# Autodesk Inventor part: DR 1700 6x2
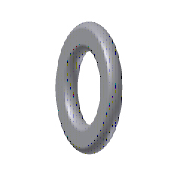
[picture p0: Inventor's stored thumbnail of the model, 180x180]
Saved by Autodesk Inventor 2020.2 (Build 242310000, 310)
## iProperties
Manager: www.cadconsulting.pl
Company: Fabian Stasiak CAD Consulting
Created: 2014-02
Part Number: DR 1700 6x2
Material: ABS-DFA-R
Description: O Ring
Document SubType Name: Modeling
Designer: F.Stasiak
Standard Revision: 1
Manufacturer: DME
Language: pl-PL
Size Designation: 6x2
Categories: <MemberInstance><Categories><Category DisplayName="Forma wtryskowa" InternalName="349578f2-f4d4-4954-8c09-8e99297a61c0" Mnemonic="MOLD"><Category DisplayName="K
Density: 1.04 g/cm^3
Appearance: Domyślna
Catalog Web Link: www.expertbooks.pl
IsCustomPart: 1
Author: F.Stasiak
Subject: Zbiór ćwiczeń. Autodesk Inventor 2020. Kurs Professional
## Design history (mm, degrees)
sketch "Sketch1"
  geometry: L1 (0, -1.4)-(0, 1.4) reference; L2 (-1, 0)-(6, 0) reference; L3 (4.6, -0.8)-(3.4, -0.8); L4 (3.4, 0.8)-(4.6, 0.8); A1 r 1 centre (4, 0) between (3.4, 0.8) and (3.4, -0.8); A2 r 1 centre (4, 0) between (4.6, 0.8) and (3.4, 0.8); A3 r 1 centre (4, 0) between (4.6, -0.8) and (4.6, 0.8); A4 r 1 centre (4, 0) between (3.4, -0.8) and (4.6, -0.8); 1 further point
  constraints: 8 point on circle, 4 centre point, 4 end point, 3 parallel, 1 point on line
  dimensions: "d3" = 8 diameter of A1.centre L1 (= dx + d2); "d9" = 2 diameter of A1 (= d2); "d20" = 1.6 distance between parallel lines of L3 L4 (= t_CS)
revolve "Revolution1" sketch "Sketch1" stored, may be unused: angle "d24" = 90 deg
sketch "Sketch2"
  geometry: L1 (-6.645, 0)-(7.668, 0) reference; L2 (0, -1.128)-(0, 1.166) reference; L3 (-4.6, 0.8)-(4.6, 0.8) reference; L4 (-4.6, -0.8)-(4.6, -0.8) reference; L5 (2.377, 0.8)-(5.623, 0.8); L6 (5.424, 0.617)-(5.3, -0.8); L7 (2.7, -0.8)-(5.3, -0.8); L8 (2.576, 0.617)-(2.7, -0.8); L9 (2.7, -0.8)-(2.7, 0.8); L10 (5.3, -0.8)-(5.3, 0.8); A1 r 1 centre (4, 0) between (4.6, -0.8) and (4.6, 0.8) reference; A2 r 0.2 centre (5.623, 0.6) between (5.623, 0.8) and (5.424, 0.617); A3 r 0.2 centre (2.377, 0.6) between (2.576, 0.617) and (2.377, 0.8); 1 further point
  constraints: 12 end point, 5 point on line, 4 point on circle, 4 tangent, 2 centre point, 2 perpendicular, 1 midpoint, 1 parallel, 1 vertical alignment
  dimensions: "d13" = 0.2 radius of A2 (= d100); "d14" = 0.2 radius of A3 (= d13); "d15" = 5 deg angle of L8 L9 (= d101); "d16" = 5 deg angle of L6 L10 (= d15); "d17" = 2.6 distance of L7.start L6.end (= b_CS)
feature "RevolutionSrf1" sketch "Sketch2" dims angle "d18" = 90 deg
fillet "Fillet1" dims "d19" = 0.3 (= r)
fillet "Fillet2" dims "d23" = 0.3
body "Solid1"
body "Srf1"
other parameters: "dx" = 6 [user parameter; used in 1 equation term], "d2" = 2 [user parameter; used in 2 equation terms], "b_CS" = 2.6 [user parameter; used in 1 equation term], "t_CS" = 1.6 [user parameter; used in 1 equation term], "d21" = 0, "d22" = 0, "r" = 0.3 [user parameter; used in 1 equation term], "d100" = 0.2 [user parameter; used in 1 equation term], "d101" = 5 deg [user parameter; used in 1 equation term]
